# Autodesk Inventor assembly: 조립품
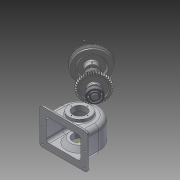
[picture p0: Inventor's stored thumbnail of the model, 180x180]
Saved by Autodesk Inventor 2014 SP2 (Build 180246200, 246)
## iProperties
Created: 2015-09
Part Number: 조립품
Document SubType Name: Assembly
Designer: 201-01
Author: 201-01
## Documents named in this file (9)
- C:\Users\201-01\Desktop\450907V1011\조립품.iam
- C:\Users\201-01\Desktop\450907V1011\본체.ipt
- C:\Users\201-01\Desktop\450907V1011\축.ipt
- C:\Users\201-01\Desktop\450907V1011\V-벨트풀리.ipt
- C:\Users\201-01\Desktop\450907V1011\베어링 6203.ipt
- C:\Users\201-01\Desktop\450907V1011\스퍼기어.ipt
- C:\Users\201-01\Desktop\450907V1011\키 - 6 x 6 x 22.ipt
- C:\Users\201-01\Desktop\450907V1011\키 - 5 x 5 x 18.ipt
- C:\Users\201-01\Desktop\450907V1011\멈춤나사 - M4x10.ipt
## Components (1 placed, 1 different names)
1. V-벨트풀리:1
